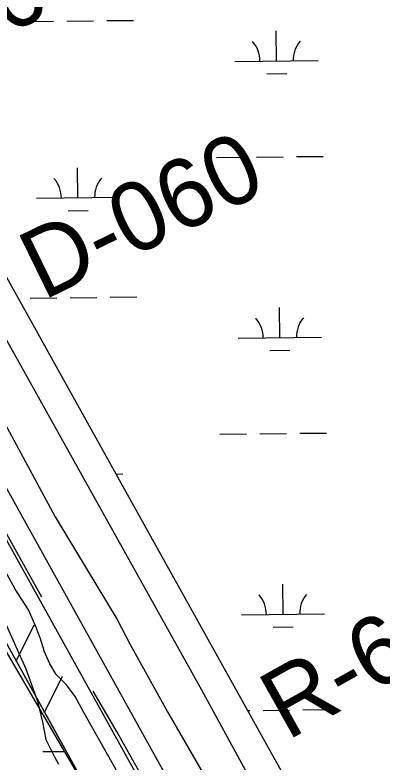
# Model space of a CAD drawing. Extents: x 3684037 to 3722149, y 433263 to 459021.
# Drawn here: x 3712366 to 3712807, y 440224 to 441123 of the extents above; entities that cross this region are included whole.
import ezdxf

# ---------------------------------------------------------------- set-up
doc = ezdxf.new("R2010")
doc.units = 0
for name, color, linetype in [('V-FLOD-BASE', 7, 'Continuous'), ('V-LEVE-TOET', 7, 'Continuous'), ('V-RIVR-EDGE', 7, 'Continuous'), ('V-RIVR-RANG-IDEN', 7, 'Continuous'), ('V-ROAD-CNTR', 7, 'Continuous'), ('V-RRAP-FSHR', 7, 'Continuous'), ('V-SITE-VEGE', 7, 'Continuous'), ('V-SURV-LINE', 7, 'Continuous'), ('V-UTIL-IDEN', 7, 'Continuous'), ('V-WETL-SWMP', 7, 'Continuous')]:
    doc.layers.add(name, color=color, linetype=linetype)

msp = doc.modelspace()

# ---------------------------------------------------------------- linework, layer by layer
at = {"layer": 'V-FLOD-BASE'}
for points in [[(3712398.74, 440422.41), (3712290.71, 440616.44), (3712177.45, 440821.47), (3712056.06, 441040.41), (3711925.95, 441279.62), (3711796.44, 441506.66), (3711752.3, 441587.16), (3711730.23, 441628.29), (3711718.6, 441652.61), (3711654.1, 441794.53), (3711570.43, 441978.74), (3711454.8, 442224.92)], [(3712621.19, 440024.51), (3712489.35, 440260.24), (3712460.31, 440309.47)]]:
    msp.add_lwpolyline(points, dxfattribs=at)
at = {"layer": 'V-LEVE-TOET'}
for points in [[(3711516.68, 442246.95), (3711627.09, 442006.55), (3711773.51, 441696.66), (3711965.19, 441335.23), (3712141.19, 441012.62), (3712263.15, 440800.06), (3712414.75, 440519.15), (3712489.08, 440395.79), (3712504.77, 440365.67), (3712551.23, 440281.69), (3712698.85, 440026.88)], [(3712594.9, 440025.08), (3712449.12, 440283.98), (3712438.67, 440303.09), (3712428.22, 440316.99), (3712416.03, 440329.72), (3712408.48, 440342.46), (3712402.09, 440356.95), (3712396.85, 440373.75), (3712391.04, 440388.23), (3712382.9, 440407.34), (3712366.65, 440432.25), (3712222.6, 440696.36), (3712039.64, 441028.82), (3711814.87, 441429.61), (3711723.69, 441588.89), (3711716.72, 441602.79), (3711694.64, 441649.13), (3711565.06, 441926.01), (3711441.87, 442202.32)]]:
    msp.add_lwpolyline(points, dxfattribs=at)
at = {"layer": 'V-RIVR-EDGE'}
msp.add_spline([(3710881.85, 442907.17), (3710900.3, 442872.76), (3710912.89, 442844.25), (3710926.84, 442815.27), (3710939.89, 442789.92), (3710950.22, 442762.31), (3710961.88, 442723.85), (3710972.69, 442706.64), (3710987.55, 442681.29), (3711004.19, 442645.52), (3711013.15, 442612.95), (3711017.62, 442590.33), (3711028.39, 442559.55), (3711043.23, 442525.61), (3711061.24, 442493.46), (3711083.32, 442464.01), (3711101.79, 442435.48), (3711123.37, 442385.69), (3711146.29, 442329.57), (3711160.2, 442285.22), (3711177.71, 442238.15), (3711205.6, 442178.4), (3711227.63, 442127.25), (3711258.71, 442079.24), (3711273.08, 442038.51), (3711277.08, 442009.57), (3711279.27, 441982.43), (3711285.11, 441965.69), (3711299.53, 441946.66), (3711314.4, 441925.82), (3711322.93, 441901.39), (3711344.09, 441864.26), (3711361.61, 441818.09), (3711381.38, 441766.05), (3711387.6, 441724.88), (3711408.3, 441685.04), (3711430.33, 441634.35), (3711446.97, 441597.23), (3711483.42, 441524.79), (3711505.9, 441474.1), (3711521.64, 441439.69), (3711545.49, 441393.97), (3711577.41, 441319.28), (3711605.29, 441255.01), (3711666.49, 441137.74), (3711693.94, 441084.32), (3711722.25, 441011.45), (3711736.18, 440977.51), (3711773.54, 440908.24), (3711800.07, 440850.29), (3711813.99, 440812.28), (3711827.94, 440785.11), (3711836.49, 440767.46), (3711872.07, 440711.3), (3711903.57, 440647.92), (3711936.4, 440576.4), (3711963.82, 440513.48), (3711991.74, 440467.29), (3712009.3, 440437.41), (3712020.05, 440394.43), (3712026.76, 440365.47), (3712043.42, 440336.04), (3712066.37, 440292.58), (3712088.89, 440257.25), (3712109.18, 440235.05), (3712138.9, 440183.88), (3712150.57, 440149.03), (3712155.9, 440111.04), (3712162.18, 440090.68), (3712177.89, 440044.52), (3712191.39, 440016), (3712212.53, 439972.54), (3712246.76, 439918.65), (3712265.21, 439881.98), (3712282.72, 439834), (3712320.51, 439756.14), (3712342.1, 439710.42), (3712373.62, 439655.63), (3712403.35, 439610.34), (3712425.83, 439558.28), (3712451.47, 439505.77), (3712470.39, 439476.33), (3712503.75, 439435.1), (3712518.6, 439408.84), (3712544.23, 439350.45), (3712559.09, 439322.83), (3712605.51, 439263.94), (3712623.98, 439233.6), (3712641.51, 439193.31), (3712662.18, 439142.17), (3712689.17, 439086.03), (3712722.5, 439033.5), (3712753.58, 438981.88), (3712765.15, 438962.6)], degree=3, dxfattribs=at)
at = {"layer": 'V-ROAD-CNTR'}
msp.add_lwpolyline([(3710393.02, 444727.69), (3710641.61, 444250), (3710817.86, 443893.88), (3711037.73, 443419.98), (3711197.76, 443070.03), (3711490.99, 442422.97), (3711750.12, 441857.32), (3711840.88, 441668.92), (3712186.17, 441036.48), (3712590.75, 440311.07), (3712879.98, 439780.16), (3713036.49, 439491.2), (3713175.22, 439193.41), (3713278.17, 438972.16)], dxfattribs=at)
at = {"layer": 'V-RRAP-FSHR'}
for p, q in [((3712368.11, 440345.47), (3712389.58, 440389.33)), ((3712368.11, 440345.47), (3712389.58, 440389.33)), ((3712402.18, 440283.79), (3712423.65, 440327.65)), ((3712402.18, 440283.79), (3712423.65, 440327.65))]:
    msp.add_line(p, q, dxfattribs=at)
for points in [[(3710219.36, 444700.16), (3710405.05, 444328.82), (3710632.08, 443905.61), (3710829.82, 443472.46), (3710874.19, 443372.05), (3710940.18, 443211.19), (3711150.7, 442775.78), (3711369.41, 442270.41), (3711583.94, 441827.2), (3711640.29, 441693.5), (3711911.6, 441196.46), (3712334.08, 440407.06), (3712777.04, 439605.31), (3712909.03, 439353.17), (3713100.31, 438966.64)], [(3712091.06, 440861.14), (3712334.08, 440407.06), (3712426.09, 440240.53)]]:
    msp.add_lwpolyline(points, dxfattribs=at)
at = {"layer": 'V-SITE-VEGE'}
for p, q in [((3712350.92, 440401.11), (3712379.55, 440336.27)), ((3712379.55, 440336.27), (3712393.45, 440297.53)), ((3712393.45, 440297.53), (3712399.74, 440272.3)), ((3712399.74, 440272.3), (3712403.66, 440251.26)), ((3712403.66, 440251.26), (3712406.04, 440246.6)), ((3712406.04, 440246.6), (3712414.12, 440230.75)), ((3712414.12, 440230.75), (3712418.88, 440221.89))]:
    msp.add_line(p, q, dxfattribs=at)
at = {"layer": 'V-SURV-LINE'}
for points in [[(3711755.82, 441636.9), (3712986.54, 439416.05)], [(3712960.3, 439401.52), (3711729.57, 441622.37)]]:
    msp.add_lwpolyline(points, dxfattribs=at)
at = {"layer": 'V-UTIL-IDEN'}
for points in [[(3710219.36, 444700.16), (3710405.05, 444328.82), (3710632.08, 443905.61), (3710829.82, 443472.46), (3710874.19, 443372.05), (3710940.18, 443211.19), (3711150.7, 442775.78), (3711369.41, 442270.41), (3711583.94, 441827.2), (3711640.29, 441693.5), (3711911.6, 441196.46), (3712334.08, 440407.06), (3712777.04, 439605.31), (3712909.03, 439353.17), (3713100.31, 438966.64)], [(3712091.06, 440861.14), (3712334.08, 440407.06), (3712426.09, 440240.53)]]:
    msp.add_lwpolyline(points, dxfattribs=at)
at = {"layer": 'V-WETL-SWMP'}
for p, q in [((3712476.88, 441115.76), (3712508.88, 441116.13)), ((3712380.89, 441114.64), (3712412.89, 441115.01)), ((3712428.89, 441115.2), (3712460.88, 441115.57)), ((3712680.77, 441067.39), (3712680.36, 441103.38)), ((3712630.78, 441066.8), (3712730.77, 441067.97)), ((3712668.95, 441051.82), (3712692.95, 441052.1)), ((3712608.71, 440951.11), (3712640.71, 440951.48)), ((3712656.71, 440951.67), (3712688.71, 440952.04)), ((3712704.71, 440952.22), (3712736.71, 440952.6)), ((3712442.2, 440902.74), (3712441.78, 440938.73)), ((3712392.21, 440902.15), (3712492.2, 440903.32)), ((3712430.38, 440887.17), (3712454.38, 440887.45)), ((3712347.94, 440821.59), (3712529.3, 440495.9)), ((3712384.76, 440781.99), (3712416.76, 440782.36)), ((3712432.76, 440782.55), (3712464.75, 440782.92)), ((3712480.75, 440783.11), (3712512.75, 440783.48)), ((3712684.65, 440734.73), (3712684.23, 440770.73)), ((3712634.65, 440734.15), (3712734.64, 440735.31)), ((3712672.83, 440719.16), (3712696.82, 440719.44)), ((3712205.56, 440614.23), (3712487.72, 440130.65)), ((3712612.59, 440618.45), (3712644.58, 440618.83)), ((3712660.58, 440619.01), (3712692.58, 440619.39)), ((3712708.58, 440619.57), (3712740.58, 440619.94)), ((3712487.72, 440570.57), (3712496.07, 440570.67)), ((3712529.3, 440495.9), (3712717.61, 440157.75)), ((3712688.52, 440402.08), (3712688.1, 440438.08)), ((3712638.52, 440401.5), (3712738.51, 440402.66)), ((3712676.7, 440386.51), (3712700.7, 440386.79)), ((3712646.11, 440286.15), (3712648.45, 440286.17)), ((3712664.45, 440286.36), (3712696.45, 440286.73)), ((3712712.45, 440286.92), (3712744.45, 440287.29)), ((3712400, 440236.86), (3712425.58, 440237.16))]:
    msp.add_line(p, q, dxfattribs=at)
for centre, start, end in [((3712625.53, 441067.22), 359.89487, 41.43853), ((3712736.01, 441068.5), 139.89486, 181.43852), ((3712386.96, 440902.57), 359.89487, 41.43853), ((3712497.44, 440903.85), 139.89486, 181.43852), ((3712629.4, 440734.57), 359.89487, 41.43853), ((3712739.88, 440735.85), 139.89486, 181.43852), ((3712633.27, 440401.91), 359.89487, 41.43853), ((3712743.75, 440403.2), 139.89486, 181.43852)]:
    msp.add_arc(centre, 35.25, start, end, dxfattribs=at)

# ---------------------------------------------------------------- texts
at = {"layer": 'V-RIVR-RANG-IDEN'}
for s, rotation, p in [('R-63.9', 27.35748, (3712253.33, 441044.35)), ('D-060', 26.05533, (3712400.3, 440778.79)), ('R-63.7', 29.23958, (3712693.5, 440249.51))]:
    msp.add_text(s, height=83, rotation=rotation, dxfattribs=at).set_placement(p)

doc.saveas('drawing.dxf')
